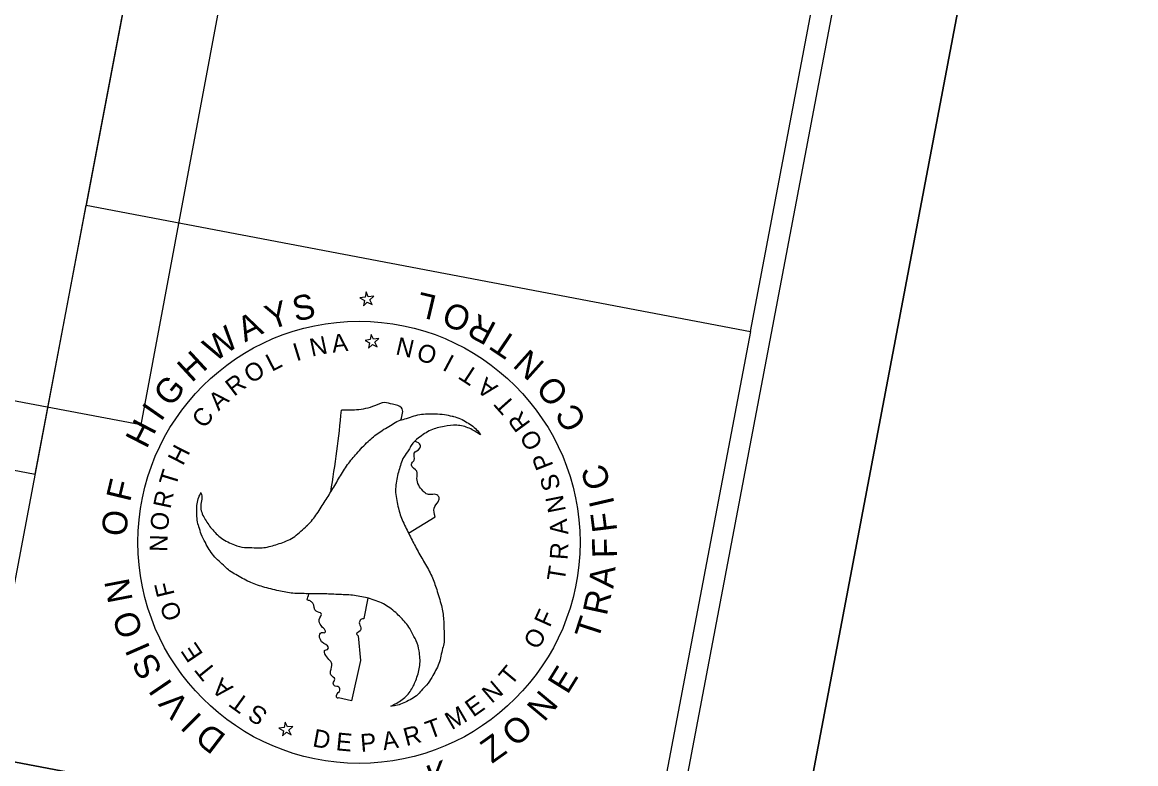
# Model space of a CAD drawing. Extents: x 1615642 to 1617075, y 899305 to 901510.
# Drawn here: x 1616848.8 to 1617075.3, y 900619.3 to 900770.1 of the extents above; entities that cross this region are included whole.
import ezdxf

# ---------------------------------------------------------------- set-up
doc = ezdxf.new("R2010")
doc.units = 0
for name, color, linetype in [('DEV BORDER CELL', 7, 'Continuous'), ('DEV DOT SWIRL SEAL CELL', 7, 'Continuous'), ('Sheet Clip Boundary CELL', 7, 'Continuous'), ('Sheet Plan CELL', 7, 'Continuous'), ('Sheet Plot Border Outside CELL', 7, 'Continuous'), ('Text', 7, 'Continuous')]:
    doc.layers.add(name, color=color, linetype=linetype)

msp = doc.modelspace()

# ---------------------------------------------------------------- linework, layer by layer
at = {"layer": 'DEV BORDER CELL'}
for points in [[(1616014.55, 901139.21), (1615734.74, 899665.53), (1616766.32, 899469.67), (1617046.12, 900943.35)], [(1616905.88, 900964.73), (1616861.86, 900732.87), (1616996.95, 900707.23), (1617040.97, 900939.08)], [(1616840.59, 900620.87), (1616861.86, 900732.87), (1616996.95, 900707.23), (1616975.68, 900595.22)], [(1616803.28, 900424.35), (1616840.59, 900620.87), (1616975.68, 900595.22), (1616938.37, 900398.7)]]:
    msp.add_lwpolyline(points, close=True, dxfattribs=at)
at = {"layer": 'DEV DOT SWIRL SEAL CELL'}
for p, q in [((1616918.77, 900715.25), (1616918.56, 900714.19)), ((1616919.23, 900714.26), (1616918.77, 900715.25)), ((1616918.56, 900714.19), (1616917.51, 900714.02)), ((1616917.51, 900714.02), (1616918.44, 900713.51)), ((1616918.44, 900713.51), (1616918.23, 900712.45)), ((1616918.23, 900712.45), (1616919.03, 900713.2)), ((1616919.03, 900713.2), (1616920, 900712.69)), ((1616920.32, 900714.39), (1616919.23, 900714.26)), ((1616919.52, 900713.63), (1616920.32, 900714.39)), ((1616920, 900712.69), (1616919.52, 900713.63)), ((1616919.62, 900705.56), (1616918.56, 900705.39)), ((1616918.56, 900705.39), (1616919.49, 900704.89)), ((1616919.82, 900706.62), (1616919.62, 900705.56)), ((1616920.28, 900705.64), (1616919.82, 900706.62)), ((1616921.37, 900705.76), (1616920.28, 900705.64)), ((1616920.58, 900705.01), (1616921.37, 900705.76)), ((1616919.49, 900704.89), (1616919.29, 900703.83)), ((1616919.29, 900703.83), (1616920.08, 900704.57)), ((1616920.08, 900704.57), (1616921.05, 900704.06)), ((1616921.05, 900704.06), (1616920.58, 900705.01)), ((1616927.43, 900666.17), (1616932.82, 900669.53)), ((1616918.41, 900648.8), (1616919.23, 900652.93)), ((1616917.17, 900645.27), (1616917.66, 900640.28)), ((1616917.66, 900640.28), (1616915.79, 900632.1)), ((1616915.79, 900632.1), (1616913.19, 900632.68)), ((1616902.1, 900626.67), (1616901.05, 900626.51)), ((1616901.05, 900626.51), (1616901.98, 900626)), ((1616902.31, 900627.74), (1616902.1, 900626.67)), ((1616902.77, 900626.75), (1616902.31, 900627.74)), ((1616903.86, 900626.87), (1616902.77, 900626.75)), ((1616903.06, 900626.12), (1616903.86, 900626.87)), ((1616903.54, 900625.18), (1616903.06, 900626.12)), ((1616901.98, 900626), (1616901.78, 900624.94)), ((1616901.78, 900624.94), (1616902.57, 900625.69)), ((1616902.57, 900625.69), (1616903.54, 900625.18))]:
    msp.add_line(p, q, dxfattribs=at)
for start, end in [(350.4529, 354.5729), (344.9279, 345.2256)]:
    msp.add_arc((1616681.63, 900713.24), 233.19, start, end, dxfattribs=at)
for points in [[(1616925.85, 900689.2), (1616926.01, 900691.68), (1616924.16, 900692.4), (1616922.56, 900692.74), (1616920.51, 900692.09), (1616916.81, 900691.24), (1616913.77, 900691.18)], [(1616885.09, 900674.44), (1616885.15, 900674.35), (1616885.14, 900671.73), (1616885.9, 900669.21), (1616887.35, 900667.1), (1616889.36, 900665.16), (1616892, 900663.79), (1616894.06, 900663.26), (1616895.09, 900663.25), (1616896.88, 900663.16), (1616898.33, 900663.29), (1616901.12, 900664.05), (1616903.92, 900665.29), (1616906.42, 900667.39), (1616906.62, 900667.57), (1616908.56, 900669.82), (1616910.25, 900672.43), (1616911.82, 900674.91), (1616913.38, 900677.54), (1616915.02, 900680.12), (1616916.87, 900682.4), (1616919.19, 900684.83), (1616921.43, 900686.67), (1616924.06, 900688.3), (1616925.37, 900689.03), (1616926.65, 900689.42), (1616929.69, 900690.32), (1616932.83, 900690.43), (1616934.72, 900690.32), (1616936.29, 900689.97), (1616936.55, 900689.92), (1616939.3, 900688.71), (1616941.48, 900686.96), (1616942.02, 900686.2)], [(1616942.02, 900686.2), (1616939.76, 900687.51), (1616937.22, 900688.12), (1616934.64, 900687.9), (1616931.95, 900687.13), (1616929.47, 900685.55), (1616927.98, 900684.03), (1616927.45, 900683.12), (1616926.46, 900681.67), (1616925.87, 900680.28), (1616925.1, 900677.53), (1616924.79, 900674.45), (1616925.36, 900671.25), (1616925.42, 900670.99), (1616926.44, 900668.18), (1616927.8, 900665.43), (1616929.16, 900662.79), (1616930.68, 900660.13), (1616932.13, 900657.42), (1616933.14, 900654.69), (1616934.09, 900651.45), (1616934.55, 900648.6), (1616934.65, 900645.52), (1616934.64, 900643.99), (1616934.34, 900642.71), (1616933.59, 900639.66), (1616932.13, 900636.85), (1616931.1, 900635.29), (1616929.97, 900634.12), (1616929.8, 900633.9), (1616927.41, 900632.12), (1616924.81, 900631.11), (1616923.83, 900630.99)], [(1616932.82, 900669.53), (1616932.64, 900671.29), (1616933.43, 900672.58), (1616933.66, 900673.23), (1616933.35, 900673.86), (1616931.24, 900674.09), (1616930.36, 900674.75), (1616929.12, 900677.31), (1616929.08, 900678.76), (1616927.99, 900680.03), (1616928.1, 900680.44), (1616928.58, 900681.01), (1616928.57, 900682.48), (1616929.71, 900683.44), (1616929.78, 900684.12), (1616928.83, 900684.85)], [(1616923.83, 900630.99), (1616926.14, 900632.33), (1616927.91, 900634.21), (1616929.01, 900636.54), (1616929.7, 900639.28), (1616929.57, 900642.22), (1616928.98, 900644.28), (1616928.5, 900645.19), (1616927.68, 900646.76), (1616926.81, 900647.94), (1616924.8, 900650.02), (1616922.29, 900651.8), (1616919.26, 900652.93), (1616919, 900653), (1616916.04, 900653.54), (1616912.98, 900653.71), (1616910.03, 900653.83), (1616906.95, 900653.87), (1616903.91, 900653.96), (1616901.02, 900654.45), (1616897.76, 900655.26), (1616895.03, 900656.27), (1616892.3, 900657.74), (1616891.02, 900658.51), (1616890.04, 900659.4), (1616887.76, 900661.61), (1616886.08, 900664.25), (1616885.25, 900665.94), (1616884.78, 900667.48), (1616884.69, 900667.74), (1616884.32, 900670.71), (1616884.74, 900673.47), (1616885.15, 900674.35)], [(1616913.19, 900632.68), (1616912.93, 900632.64), (1616912.74, 900633.14), (1616913.47, 900634.27), (1616913.06, 900634.98), (1616912.52, 900635.05), (1616912.09, 900635.65), (1616912.42, 900636.45), (1616911.61, 900637.38), (1616911.55, 900638.11), (1616911.83, 900639.58), (1616910.41, 900641.66), (1616910.44, 900642.4), (1616910.95, 900642.51), (1616911.12, 900642.94), (1616909.82, 900643.99), (1616909.66, 900644.22), (1616909.36, 900645.66), (1616909.71, 900645.97), (1616910.37, 900645.96), (1616910.51, 900646.13), (1616910.29, 900646.63), (1616909.63, 900647.39), (1616909.26, 900648.61), (1616909.67, 900649.86), (1616908.65, 900650.28), (1616907.94, 900651.97), (1616907.39, 900652.39), (1616906.79, 900652.59)], [(1616918.41, 900648.8), (1616917.71, 900648.59), (1616917.39, 900647.96), (1616917.69, 900646.95), (1616917.54, 900646.29), (1616916.84, 900645.65), (1616917.17, 900645.27)]]:
    msp.add_spline(points, degree=3, dxfattribs=at)
at = {"layer": 'Sheet Clip Boundary CELL'}
msp.add_lwpolyline([(1616176.29, 901060.7), (1616913.78, 900900.04), (1616896.28, 900812.91), (1616872.94, 900688.21), (1616835.87, 900695.21), (1616753.94, 900262.18), (1616898.09, 900233.43), (1616663.91, 899565.73), (1616252.62, 899604.04), (1615894.68, 899796.73), (1615981.58, 900932.46), (1616145.94, 900899.57)], close=True, dxfattribs=at)
at = {"layer": 'Sheet Plan CELL'}
msp.add_lwpolyline([(1616859.19, 900973.59), (1616804.79, 900687.04), (1616851.47, 900678.18), (1616905.88, 900964.73)], close=True, dxfattribs=at)
at = {"layer": 'Sheet Plot Border Outside CELL'}
for points in [[(1616760.47, 899304.87), (1615679.78, 899510.06), (1615994.65, 901168.43), (1617075.34, 900963.24)], [(1616760.47, 899304.87), (1617075.34, 900963.24), (1615994.65, 901168.43), (1615679.78, 899510.06)]]:
    msp.add_lwpolyline(points, close=True, dxfattribs=at)
at = {"layer": 'Text'}
msp.add_circle((1616917.34, 900664.32), 44.97, dxfattribs=at)

# ---------------------------------------------------------------- texts
at = {"layer": 'DEV DOT SWIRL SEAL CELL'}
for s, height, rotation, p in [('S', 5.04, 12.4743, (1616904.4, 900709.18)), ('Y', 5.04, 18.9977, (1616899.33, 900707.45)), ('A', 5.04, 26.0256, (1616894.13, 900704.96)), ('W', 5.04, 35.0626, (1616887.96, 900700.86)), ('N', 3.63, 12.1007, (1616907.73, 900702.07)), ('A', 3.63, 7.0227, (1616912.01, 900702.88)), ('N', 3.63, 166.9823, (1616928.85, 900705.33)), ('H', 5.04, 42.7126, (1616883.29, 900696.66)), ('I', 3.63, 17.1788, (1616904.59, 900701.12)), ('O', 3.63, 162.1763, (1616933.52, 900703.81)), ('O', 3.63, 32.4131, (1616895.39, 900696.49)), ('L', 3.63, 27.335, (1616899.6, 900698.96)), ('I', 3.63, 152.0201, (1616937.01, 900702.05)), ('T', 3.63, 146.942, (1616941.93, 900699.08)), ('G', 5.04, 50.7661, (1616879.02, 900691.62)), ('R', 3.63, 37.4912, (1616891.93, 900693.88)), ('A', 3.63, 141.8639, (1616945.78, 900696.08)), ('A', 3.63, 42.5693, (1616888.77, 900690.92)), ('I', 5.04, 55.0534, (1616877.05, 900688.7)), ('T', 3.63, 131.7077, (1616949.3, 900692.41)), ('C', 3.63, 52.7254, (1616885.92, 900687.29)), ('R', 3.63, 126.6297, (1616952.37, 900688.51)), ('H', 5.04, 62.7034, (1616874.1, 900683.16)), ('O', 3.63, 121.5516, (1616954.91, 900684.44)), ('H', 3.63, 62.8816, (1616881.51, 900679.75)), ('P', 3.63, 111.3954, (1616956.93, 900679.91)), ('S', 3.63, 106.3173, (1616958.42, 900675.42)), ('F', 5.04, 76.5069, (1616870.74, 900672.37)), ('R', 3.63, 78.1158, (1616878.97, 900670.99)), ('N', 3.63, 101.2392, (1616959.44, 900670.73)), ('O', 5.04, 85.0143, (1616869.99, 900665.43)), ('O', 3.63, 83.1939, (1616878.41, 900666.54)), ('A', 3.63, 96.1611, (1616959.95, 900665.98)), ('N', 3.63, 88.272, (1616878.34, 900662.34)), ('R', 3.63, 86.005, (1616959.73, 900660.67)), ('T', 3.63, 80.9269, (1616959.13, 900656.22)), ('N', 5.04, 100.8354, (1616871.34, 900652.55)), ('F', 3.63, 103.5063, (1616879.87, 900653.68)), ('O', 3.63, 108.5844, (1616881.39, 900649.11)), ('O', 5.04, 109.3428, (1616873.51, 900645.92)), ('F', 3.63, 65.6926, (1616956.13, 900646.85)), ('O', 3.63, 60.6146, (1616953.76, 900642.29)), ('I', 5.04, 113.6302, (1616874.97, 900642.72)), ('E', 3.63, 123.8186, (1616885.75, 900641.55)), ('S', 5.04, 119.8342, (1616877.51, 900638.3)), ('T', 3.63, 128.8967, (1616888.47, 900638.12)), ('T', 3.63, 50.4584, (1616948.28, 900634.98)), ('I', 5.04, 124.1215, (1616879.53, 900635.42)), ('A', 3.63, 139.0529, (1616891.9, 900634.86)), ('N', 3.63, 40.3022, (1616944.31, 900631.41)), ('V', 5.04, 130.83, (1616883.1, 900631.23)), ('T', 3.63, 144.1309, (1616895.27, 900632.25)), ('E', 3.63, 35.2241, (1616940.57, 900628.64)), ('S', 3.63, 149.209, (1616899.04, 900629.92)), ('M', 3.63, 30.146, (1616936.19, 900626.07)), ('I', 5.04, 135.1173, (1616885.64, 900628.79)), ('T', 3.63, 19.9899, (1616931.68, 900624.26)), ('D', 5.04, 142.7084, (1616890.54, 900624.96)), ('D', 3.63, 349.5214, (1616907.73, 900622.83)), ('R', 3.63, 14.9118, (1616926.93, 900622.84)), ('E', 3.63, 354.5995, (1616912.53, 900622.04)), ('P', 3.63, 4.7556, (1616917.75, 900621.66)), ('A', 3.63, 9.8337, (1616922.36, 900622.01))]:
    msp.add_text(s, height=height, rotation=rotation, dxfattribs=at).set_placement(p)
at = {"layer": 'Text'}
for s, height, rotation, p in [('L', 5.04, 166.6784, (1616933.41, 900714.4)), ('O', 5.04, 158.239, (1616940.59, 900711.5)), ('R', 5.04, 152.0012, (1616945.58, 900708.69)), ('T', 5.04, 146.1304, (1616949.97, 900705.57)), ('N', 5.04, 138.1413, (1616955.38, 900700.64)), ('O', 5.04, 129.702, (1616960.3, 900694.66)), ('C', 5.04, 122.3301, (1616963.84, 900688.9)), ('T', 3.63, 73.0378, (1616880.06, 900675.5)), ('C', 5.04, 107.2527, (1616968.63, 900675.95)), ('I', 5.04, 102.9996, (1616969.35, 900672.12)), ('F', 5.04, 97.012, (1616969.88, 900666.65)), ('F', 5.04, 91.0244, (1616969.84, 900661.16)), ('A', 5.04, 84.0528, (1616969.07, 900654.81)), ('R', 5.04, 77.815, (1616967.73, 900649.24)), ('T', 5.04, 71.9442, (1616965.92, 900644.17)), ('E', 5.04, 58.201, (1616959.74, 900633.2)), ('N', 5.04, 50.212, (1616955.01, 900627.61)), ('O', 5.04, 41.7727, (1616949.21, 900622.48)), ('Z', 5.04, 35.4181, (1616944.38, 900619.21)), ('K', 5.04, 21.0412, (1616932.34, 900613.91))]:
    msp.add_text(s, height=height, rotation=rotation, dxfattribs=at).set_placement(p)

doc.saveas('drawing.dxf')
